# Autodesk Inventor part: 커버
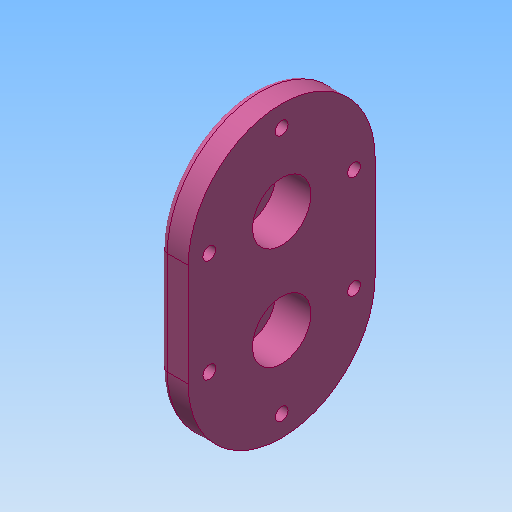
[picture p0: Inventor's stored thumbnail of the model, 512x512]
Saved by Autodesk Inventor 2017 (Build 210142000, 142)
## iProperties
Created: 2019-03
Part Number: 커버
Material: 알루미늄 6061
Document SubType Name: Modeling
Designer: mduedu
Density: 1 g/cm^3
Appearance: 분홍색
Author: mduedu
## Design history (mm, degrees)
sketch "스케치1"
  geometry: L1 (-62, 40)-(62, 40); L2 (62, 40)-(62, -40); L3 (62, -40)-(-62, -40); L4 (-62, -40)-(-62, 40); L5 (-62, 40)-(62, -40); L6 (62, 40)-(-62, -40); 1 further point
  constraints: 12 end point, 2 midpoint, 2 parallel, 1 horizontal, 1 perpendicular
  dimensions: "d59" = 124 distance of L2.end L3.end; "d60" = 80 distance of L1.end L2.end
extrude "돌출1" new body sketch "스케치1" distance "d4" = 12; taper "d5" = 0 deg
fillet "모깎기4"
fillet "모깎기5"
sketch "스케치2"
  geometry: L1 (-20, -22)-(20, -22); L2 (20, -22)-(20, 22); L3 (20, 22)-(-20, 22); L4 (-20, 22)-(-20, -22); L5 (-20, -22)-(20, 22); L6 (20, -22)-(-20, 22); 3 further points
  constraints: 12 end point, 4 midpoint, 2 horizontal alignment, 2 parallel, 1 horizontal, 1 perpendicular, 4 other
  dimensions: "d6" = 40 distance between parallel lines of L2 L4; "d8" = 44 distance between parallel lines of L1 L3
extrude "돌출2" join sketch "스케치2" distance "d9" = 10; taper "d10" = 0 deg
fillet "모깎기2" dims "d12" = 3
sketch "스케치3"
  geometry: L1 (-31, -22)-(31, -22); L2 (31, -22)-(31, 22); L3 (31, 22)-(-31, 22); L4 (-31, 22)-(-31, -22); L5 (-31, -22)-(31, 22); L6 (31, -22)-(-31, 22); A1 r 31 centre (0, 22) between (31, 22) and (0, 53); A2 r 31 centre (0, -22) between (31, -22) and (0, -53); 7 further points
  constraints: 12 end point, 6 midpoint, 4 coincident, 4 point on circle, 2 centre point, 2 parallel, 2 vertical alignment, 1 horizontal, 1 perpendicular
  dimensions: "d76" = 44 distance between parallel lines of L1 L3; "d78" = 62 distance between parallel lines of L2 L4
hole "구멍2" sketch "스케치3" at (0, 53), (31, 22), (31, -22), (-31, -22), (-31, 22), (0, -53) diameter "d28" = 5.5; stored, may be unused: countersink angle "d32" = 90 deg, drill point angle "d34" = 118 deg; dims "d29" = 6, "d30" = 4, "d31" = 2, "d33" = 8
sketch "스케치10"
  geometry: L1 (40, -22)-(40, 22) reference; L2 (-40, 22)-(-40, -22) reference; L3 (23, -22)-(23, 22) reference; L4 (-23, 22)-(-23, -22) reference; C1 r 2.75 at (-31, 22) reference; C2 r 2.75 at (31, -22) reference; C3 r 2.75 at (0, 53) reference; C4 r 2.75 at (31, 22) reference; C5 r 2.75 at (-31, -22) reference; C6 r 2.75 at (0, -53) reference; A1 r 40 centre (0, -22) between (-40, -22) and (40, -22) reference; A2 r 40 centre (0, 22) between (40, 22) and (-40, 22) reference; A3 r 23 centre (0, -22) between (-23, -22) and (23, -22) reference; A4 r 23 centre (0, 22) between (23, 22) and (-23, 22) reference; 7 further points
  constraints: 6 coincident
hole "구멍5" sketch "스케치10" at (0, 53), (31, 22), (31, -22), (0, -53), (-31, -22), (-31, 22) diameter "d79" = 11; stored, may be unused: countersink angle "d83" = 90 deg, drill point angle "d85" = 0 deg; dims "d80" = 6, "d81" = 4, "d82" = 2, "d84" = 5.4
fillet "모깎기3" dims "d68" = 3
sketch "스케치6"
  geometry: C1 r 12.5 at (0, 22); 1 further point
  constraints: 1 centre point, 1 vertical alignment
  dimensions: "d43" = 25 diameter of C1; "d45" = 22 distance of C1.centre point (0, 0)
extrude "돌출5" cut sketch "스케치6" distance "d47" = 15; taper "d48" = 0 deg
node "솔리드1"
mirror "대칭1"
node "투영된 루프5"
